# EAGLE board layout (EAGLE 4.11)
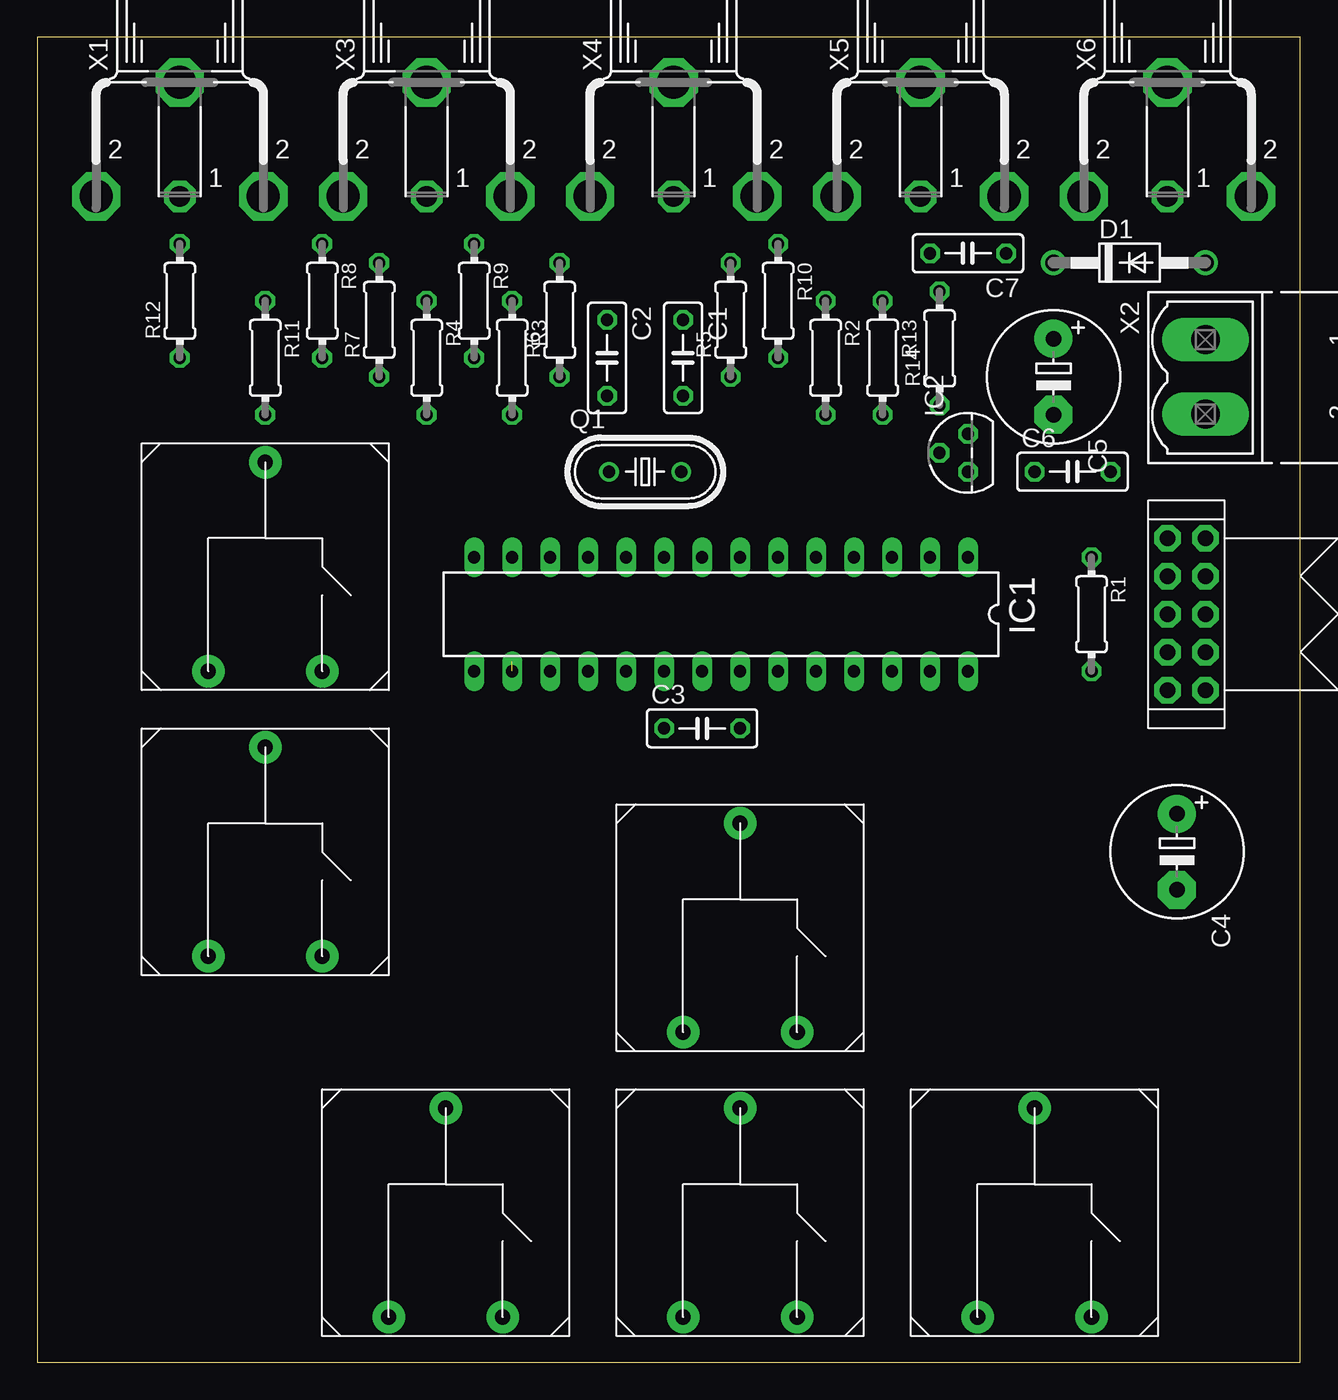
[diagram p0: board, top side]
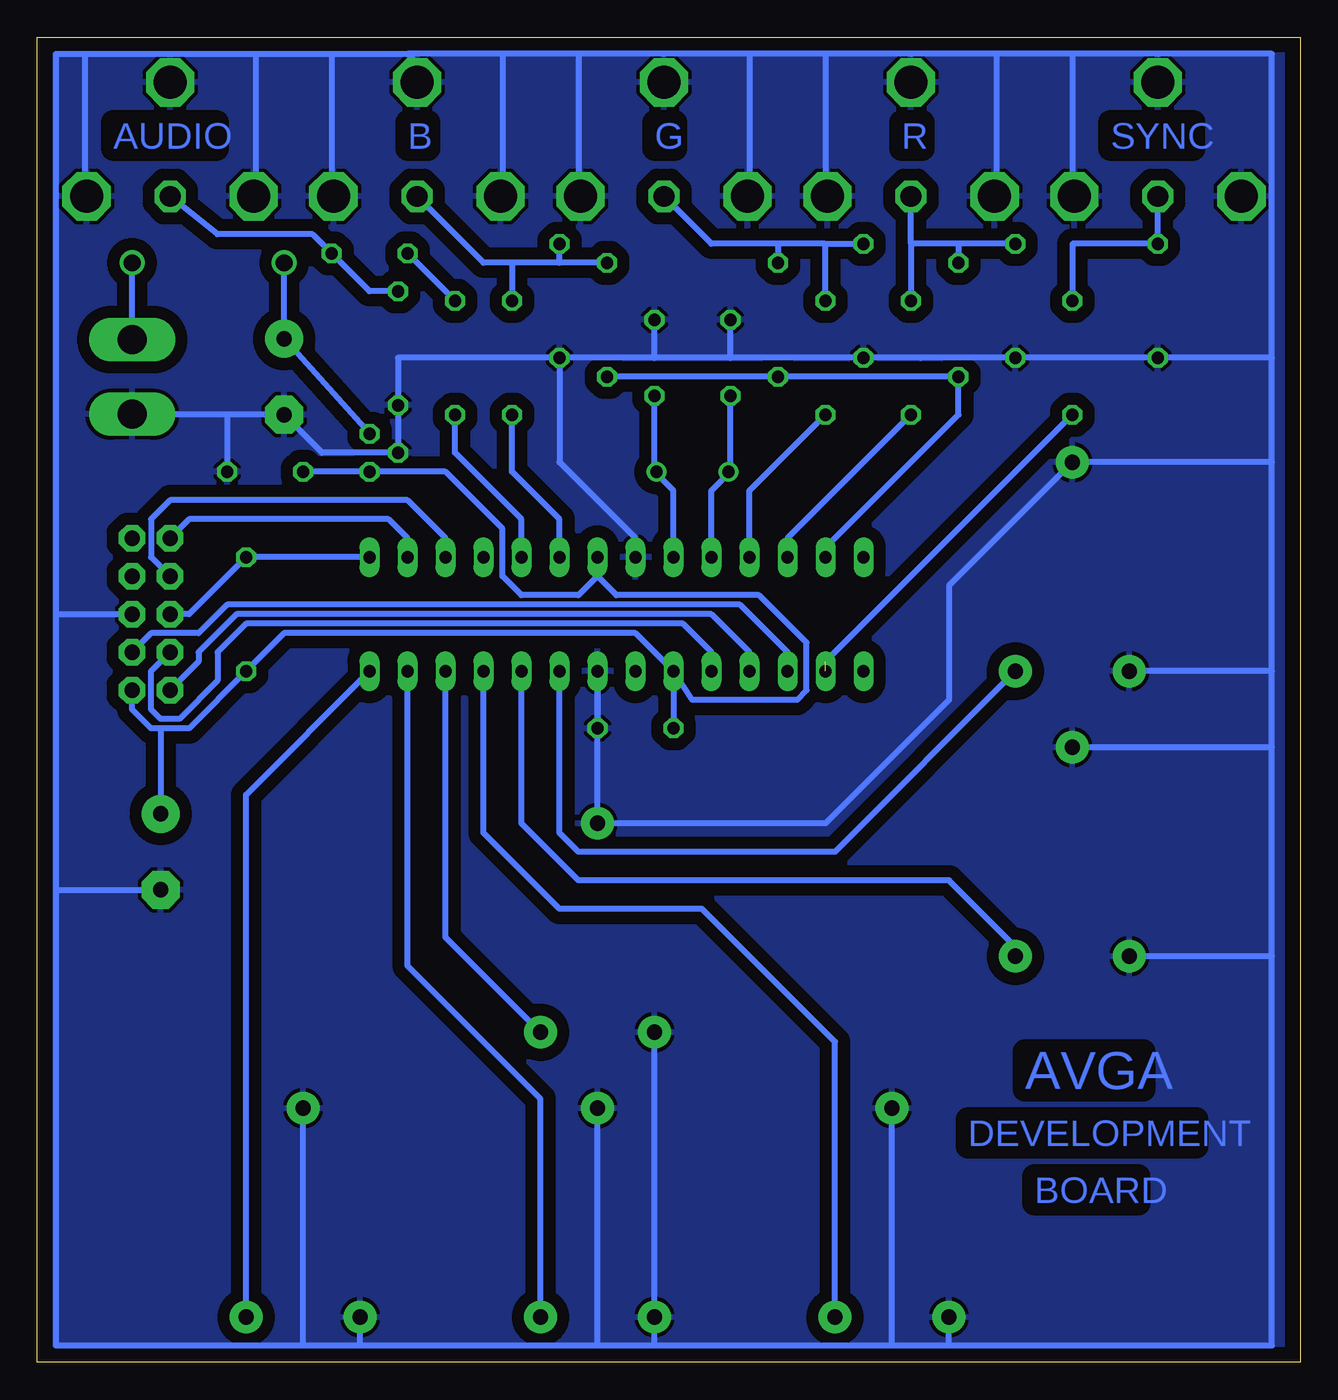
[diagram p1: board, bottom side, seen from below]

Size 84.44 x 88.57 mm. Coordinates in mm from the lower left corner, seen from the top.
Outline: 0,0 84.44,0 84.44,88.57 0,88.57 0,0
Copper layers (1*16): Top 0.035mm / dielectric 1.5mm / Bottom 0.035mm
Design rules "default": minimum track width 10mil, minimum drill 24mil, track to track 8mil, track to pad 8mil, pad to pad 8mil, via to via 8mil, smd to smd 8mil, copper to edge 40mil, drill to drill 8mil, minimum pad ring 10mil, minimum via ring 8mil, stop-mask expansion 4mil, vias tented up to drill 0mil, thermal gap 10mil

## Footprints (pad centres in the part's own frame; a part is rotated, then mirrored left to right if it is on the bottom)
C050-025X075 = drill 0.813 octagon: 1 -2.54,0; 2 2.54,0
E5-8,5 = drill 1.016 pad 2.54 round: + -2.54,0 | drill 1.016 pad 2.54 octagon: - 2.54,0
DO41-10 = drill 1.118 round: A 5.08,0; C -5.08,0
DIL28-3 = drill 0.813 long: 1 -16.51,-3.81; 2 -13.97,-3.81; 3 -11.43,-3.81; 4 -8.89,-3.81; 5 -6.35,-3.81; 6 -3.81,-3.81; 7 -1.27,-3.81; 8 1.27,-3.81; 9 3.81,-3.81; 10 6.35,-3.81; 11 8.89,-3.81; 12 11.43,-3.81; 13 13.97,-3.81; 14 16.51,-3.81; 15 16.51,3.81; 16 13.97,3.81; 17 11.43,3.81; 18 8.89,3.81; 19 6.35,3.81; 20 3.81,3.81; 21 1.27,3.81; 22 -1.27,3.81; 23 -3.81,3.81; 24 -6.35,3.81; 25 -8.89,3.81; 26 -11.43,3.81; 27 -13.97,3.81; 28 -16.51,3.81
TO92 = drill 0.813 octagon: 1 -1.27,0; 2 0,1.905; 3 1.27,0
HC49U-V = drill 0.813 round: 1 -2.413,0; 2 2.413,0
0204/7 = drill 0.813 octagon: 1 -3.81,0; 2 3.81,0
KEYBUTTON = drill 1.016 pad 2.184 round: P$3 -3.81,-6.35; P$4 3.81,-6.35; P$5 0,7.62
CON-ISP = drill 1.016 pad 1.778 octagon: 1 -5.08,1.27; 2 -5.08,-1.27; 3 -2.54,1.27; 4 -2.54,-1.27; 5 0,1.27; 6 0,-1.27; 7 2.54,1.27; 8 2.54,-1.27; 9 5.08,1.27; 10 5.08,-1.27
TOBU3 = drill 1.397 octagon: 1 0,-2.54 | drill 2.21 octagon: 2 5.588,-2.54; 2@1 -5.588,-2.54; 2@2 0,5.08
MSTBV2 = drill 1.93 pad 2.184 long: 1 -2.5,0; 2 2.5,0

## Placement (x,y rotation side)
C1  22p  [C050-025X075]  43.17,67.14 270 top
C2  22p  [C050-025X075]  38.09,67.14 270 top
C3  100n  [C050-025X075]  44.45,42.38 0 top
C4  100u  [E5-8,5]  76.2,34.12 270 top
C5  100u  [E5-8,5]  67.94,65.88 270 top
C6  100n  [C050-025X075]  69.21,59.52 0 top
C7  100n  [C050-025X075]  62.23,74.13 180 top
D1  1N4004  [DO41-10]  73.02,73.5 0 top
IC1  ATMEGA168-20P  [DIL28-3]  45.72,50 180 top
IC2  78L05Z  [TO92]  62.23,60.8 90 top
Q1  19.6608MHz  [HC49U-V]  40.63,59.52 0 top
R1  4k7  [0204/7]  70.48,50 270 top
R2  2k2  [0204/7]  52.7,67.14 270 top
R3  2k2  [0204/7]  31.75,67.14 270 top
R4  2k2  [0204/7]  26.03,67.14 270 top
R5  3k3  [0204/7]  46.35,69.69 90 top
R6  3k3  [0204/7]  34.92,69.69 90 top
R7  3k3  [0204/7]  22.86,69.69 90 top
R8  1k  [0204/7]  19.05,70.95 270 top
R9  1k  [0204/7]  29.21,70.95 270 top
R10  1k  [0204/7]  49.52,70.95 270 top
R11  1k  [0204/7]  15.24,67.14 270 top
R12  1k  [0204/7]  9.52,70.95 90 top
R13  22k  [0204/7]  56.51,67.14 270 top
R14  10k  [0204/7]  60.32,67.78 90 top
U$1  KEYBUTTON  [KEYBUTTON]  66.67,9.36 0 top
U$2  KEYBUTTON  [KEYBUTTON]  46.98,9.36 0 top
U$3  KEYBUTTON  [KEYBUTTON]  46.98,28.41 0 top
U$4  KEYBUTTON  [KEYBUTTON]  27.3,9.36 0 top
U$5  KEYBUTTON  [KEYBUTTON]  15.24,33.49 0 top
U$6  KEYBUTTON  [KEYBUTTON]  15.24,52.54 0 top
U$7  CON-ISP  [CON-ISP]  76.83,50 90 top
X1  TOBU3  [TOBU3]  9.52,80.48 0 top
X2  [MSTBV2]  78.1,65.88 270 top
X3  TOBU3  [TOBU3]  26.03,80.48 0 top
X4  TOBU3  [TOBU3]  42.54,80.48 0 top
X5  TOBU3  [TOBU3]  59.05,80.48 0 top
X6  TOBU3  [TOBU3]  75.56,80.48 0 top

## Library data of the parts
C1-C7 R1-R14 = rcl
D1 = diode
IC1 = avr
IC2 = linear
Q1 = crystal
U$1-U$6 = keybutton
U$7 = con-isp
X1 X3-X6 = con-hirschmann
X2 = con-phoenix-500

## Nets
B: R2.1 R5.2 R10.1 X5.1
G: R3.1 R6.2 R9.1 X4.1
GND: C1.1 C2.1 C3.2 C4.- C5.- C6.2 IC1.8 IC1.22 IC2.2 R8.2 R9.2 R10.2 R12.1 R14.1 U$1.P$3 U$1.P$5 U$2.P$3 U$2.P$5 U$3.P$3 U$3.P$5 U$4.P$3 U$4.P$5 U$5.P$3 U$5.P$5 U$6.P$3 U$6.P$5 U$7.6 X1.2 X1.2@1 X1.2@2 X2.2 X3.2 X3.2@1 X3.2@2 X4.2 X4.2@1 X4.2@2 X5.2 X5.2@1 X5.2@2 X6.2 X6.2@1 X6.2@2
N$1: C1.2 IC1.9 Q1.2
N$2: IC1.1 R1.1 U$7.5
N$3: C2.2 IC1.10 Q1.1
N$4: IC1.11 R3.2
N$5: IC1.6 R2.2
N$6: IC1.12 R4.2
N$7: IC1.13 R5.1 R6.1 R7.1
N$8: D1.A X2.1
N$9: IC1.23 U$6.P$4
N$10: IC1.24 U$5.P$4
N$11: IC1.25 U$4.P$4
N$12: C5.+ D1.C IC2.3
N$13: IC1.26 U$3.P$4
N$14: IC1.16 R11.2
N$15: IC1.27 U$2.P$4
N$16: IC1.28 U$1.P$4
N$17: IC1.5 R13.2
N$18: C7.2 R13.1
N$19: C7.1 R14.2 X6.1
N$29: IC1.18 U$7.1
N$30: IC1.17 U$7.4
N$31: IC1.19 U$7.3
N$32: IC1.2 U$7.9
N$33: IC1.3 U$7.7
R: R4.1 R7.2 R8.1 X3.1
SYNC: R11.1 R12.2 X1.1
VCC: C3.1 C4.+ C6.1 IC1.7 IC1.20 IC2.1 R1.2 U$7.2

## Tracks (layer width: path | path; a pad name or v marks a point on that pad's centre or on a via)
B
  Bottom 0.406: 52.7,73.5 R2.1 | X5.1 54.61,73.5 52.7,73.5 | R5.2 49.52,73.5 | 49.52,73.5 52.7,73.5 | 49.52,73.5 R10.1
G
  Bottom 0.406: R3.1 31.75,74.77 | 31.75,74.77 R9.1 | 31.75,74.77 34.92,74.77 | 34.92,74.77 R6.2 | X4.1 39.37,74.77 34.92,74.77
GND
  Bottom 0.406: IC1.8 44.45,55.08 49.52,60.16 R10.2 | 38.09,67.14 43.17,67.14 | 38.09,67.14 R9.2 R8.2 | 38.09,67.14 C2.1 | 43.17,67.14 C1.1 | R8.2 25.39,67.14 | X2.2 76.83,63.34 71.75,63.34 | 71.75,63.34 C5.- 65.4,60.8 IC2.2 | R14.1 60.32,67.14 R10.2 | R14.1 IC2.2 | 71.75,63.34 C6.2 | IC1.22 C3.2 | IC1.22 C3.2 | 1.9,27.14 1.9,1.1 23.49,1.1 | 1.9,27.14 1.9,41.11 | 1.9,41.11 1.9,46.19 | 1.9,46.19 1.9,60.16 | 1.9,60.16 1.9,67.14 | 46.98,1.1 62.86,1.1 | 62.86,1.1 66.67,1.1 | 66.67,1.1 83.18,1.1 83.18,31.58 | 43.17,1.1 46.98,1.1 | 83.18,31.58 83.18,50 | 83.18,50 83.18,77.94 83.18,87.47 81.28,87.47 | 15.24,87.47 9.52,87.47 1.9,87.47 1.9,67.14 | 15.24,87.47 20.32,87.47 | 20.32,87.47 26.03,87.47 31.75,87.47 | 31.75,87.47 36.83,87.47 | 36.83,87.47 42.54,87.47 48.26,87.47 | 48.26,87.47 53.34,87.47 | 53.34,87.47 59.69,87.47 | 81.28,87.47 75.56,87.47 69.84,87.47 | 64.77,87.47 59.69,87.47 | 69.84,87.47 64.77,87.47 | R8.2 R12.1 1.9,67.14 | 1.9,46.19 U$6.P$3 | 1.9,27.14 U$5.P$3 | 1.9,41.11 U$5.P$5 | C3.2 46.98,41.74 | 1.9,60.16 U$6.P$5 23.49,51.91 23.49,44.28 31.75,36.03 U$3.P$5 IC1.22 | 27.3,1.1 U$4.P$5 | 27.3,1.1 43.17,1.1 | 23.49,1.1 27.3,1.1 | 23.49,1.1 U$4.P$3 | 43.17,1.1 U$2.P$3 U$3.P$3 | 46.98,1.1 U$2.P$5 | 62.86,1.1 U$1.P$3 | 66.67,1.1 U$1.P$5 | 83.18,31.58 C4.- | 83.18,50 U$7.6 | 59.69,87.47 59.05,86.83 | 43.17,67.14 R10.2 | R14.1 IC2.2 | 15.24,87.47 15.24,77.94 | 20.32,87.47 20.32,77.94 | 31.75,87.47 31.75,77.94 | 36.83,87.47 36.83,77.94 | 48.26,87.47 48.26,77.94 | 53.34,87.47 53.34,77.94 | 64.77,87.47 64.77,77.94 | 69.84,87.47 69.84,77.94 | 81.28,87.47 81.28,77.94 | X4.2@2 41.91,85.56 | X1.2@2 10.16,85.56
  pour Bottom (isolate 0.813): -1.28,93.81 97.78,93.81 97.78,-12.23 -6.99,-12.23 -6.99,93.81
N$1
  Bottom 0.406: 43.17,59.52 Q1.2 | 43.17,59.52 C1.2 | IC1.9 41.91,58.25 43.17,59.52
N$2
  Bottom 0.406: U$7.5 74.29,50 R1.1 IC1.1
N$3
  Bottom 0.406: 38.09,59.52 Q1.1 | 38.09,59.52 C2.2 | IC1.10 39.37,58.25 38.09,59.52
N$4
  Bottom 0.406: IC1.11 36.83,58.25 R3.2
N$5
  Bottom 0.406: R2.2 52.7,59.52 49.52,56.35 IC1.6
N$6
  Bottom 0.406: IC1.12 34.29,55.08 R4.2
N$7
  Bottom 0.406: R5.1 R6.1 R7.1 22.86,63.34 31.75,54.45 IC1.13
N$8
  Bottom 0.406: X2.1 D1.A
N$9
  Bottom 0.406: U$6.P$4 31.11,34.12 48.26,34.12 49.52,35.39 IC1.23
N$10
  Bottom 0.406: IC1.24 52.06,36.03 48.26,32.22 23.49,32.22 19.05,27.77 U$5.P$4
N$11
  Bottom 0.406: IC1.25 54.61,35.39 49.52,30.31 40,30.31 31.11,21.42 U$4.P$4
N$12
  Bottom 0.406: D1.C C5.+ IC2.3
N$13
  Bottom 0.406: IC1.26 57.15,28.41 U$3.P$4
N$14  (1 unrouted)
  Bottom 0.406: 31.75,45.55 31.75,46.82 R11.2
N$15
  Bottom 0.406: IC1.27 59.69,26.5 50.8,17.61 U$2.P$4
N$16
  Bottom 0.406: U$1.P$4 70.48,37.94 IC1.28
N$17
  Bottom 0.406: R13.2 56.51,60.8 52.06,56.35 IC1.5
N$18
  Bottom 0.406: R13.1 C7.2
N$19
  Bottom 0.406: R14.2 62.23,71.59 C7.1 66.03,75.4 72.39,75.4 X6.1
N$29
  Bottom 0.406: IC1.18 36.83,47.46 39.37,50 71.11,50 73.66,47.46 73.66,46.82 U$7.1
N$30
  Bottom 0.406: IC1.17 34.29,47.46 37.46,50.63 71.75,50.63 73.66,48.73 76.83,48.73 U$7.4
N$31
  Bottom 0.406: IC1.19 39.37,47.46 41.27,49.37 70.48,49.37 72.39,47.46 72.39,45.55 74.92,43.02 76.2,43.02 76.83,43.65 76.83,46.19 U$7.3
N$32
  Bottom 0.406: IC1.2 59.69,55.08 60.95,56.35 74.29,56.35 U$7.9
N$33
  Bottom 0.406: U$7.7 76.83,53.81 76.83,56.35 75.56,57.62 59.69,57.62 57.15,55.08 IC1.3
R
  Bottom 0.406: R8.1 22.86,74.77 | 22.86,74.77 26.03,74.77 | 22.86,74.77 R7.2 | 26.03,74.77 R4.1 | 26.03,74.77 X3.1
SYNC
  Bottom 0.406: X1.1 R12.2 15.24,74.77 R11.1
VCC
  Bottom 0.406: U$7.2 78.1,43.65 76.83,42.38 76.2,42.38 | 76.2,42.38 74.29,42.38 R1.2 67.94,48.73 44.45,48.73 IC1.20 | IC1.20 C3.1 | 46.98,52.54 IC1.7 | 46.98,52.54 45.72,51.27 36.19,51.27 33.02,48.09 33.02,44.92 33.65,44.28 40.63,44.28 IC1.20 | 46.98,52.54 48.26,51.27 52.06,51.27 53.34,52.54 53.34,55.71 57.15,59.52 IC2.1 C6.1 | 76.2,42.38 C4.+

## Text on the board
Bottom: SYNC | R | G | B | AUDIO | AVGA | DEVELOPMENT | BOARD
